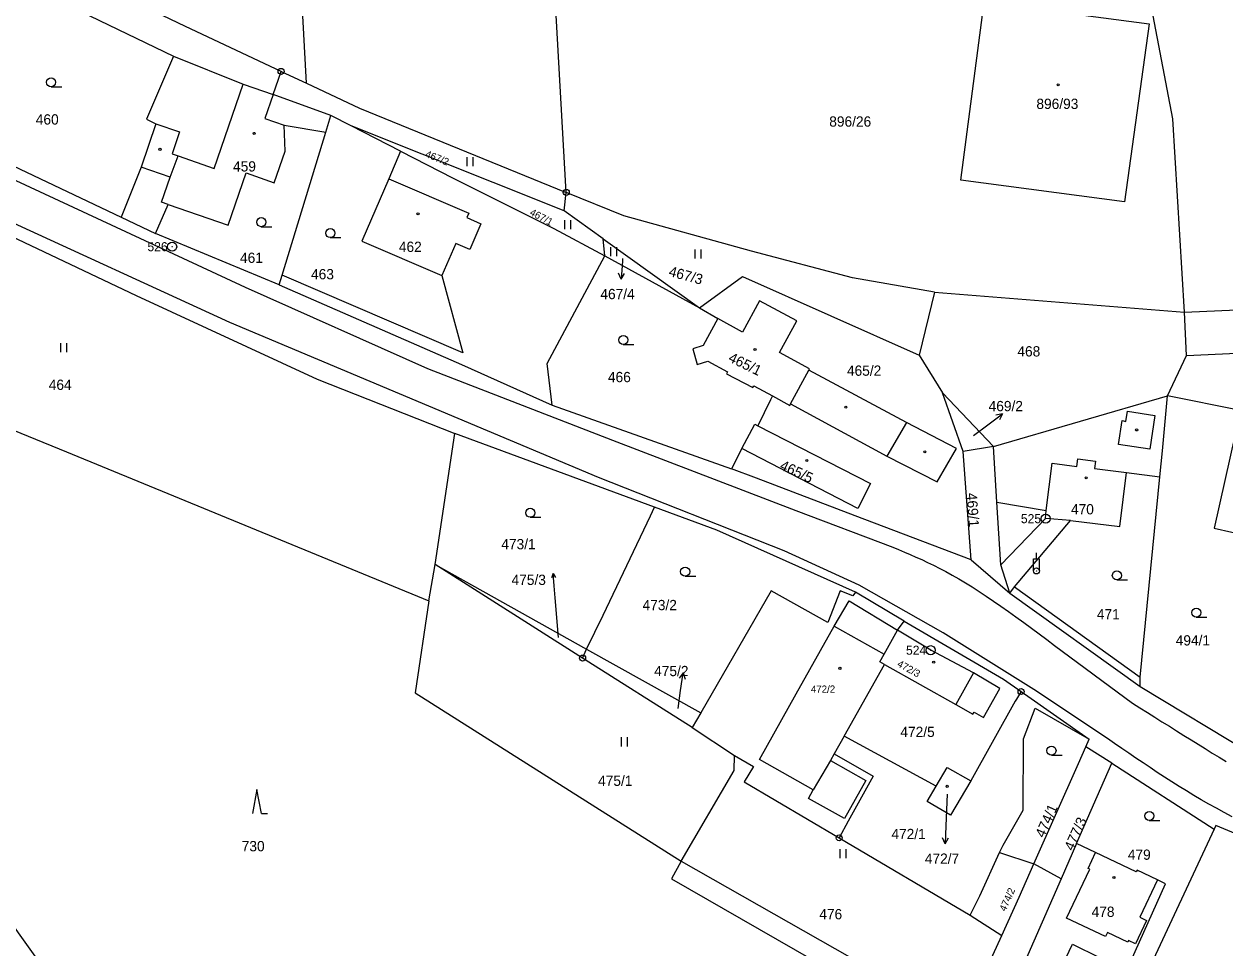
# Model space of a CAD drawing. Extents: x -504988 to -494607, y -1123820 to -1114018.
# Drawn here: x -500090 to -499891, y -1121300.2 to -1121147.2 of the extents above; entities that cross this region are included whole.
import ezdxf

# ---------------------------------------------------------------- set-up
doc = ezdxf.new("R2010")
doc.units = 0
for name, color, linetype in [('Hranice parcel', 7, 'Continuous'), ('Parcelní čísla', 7, 'Continuous'), ('Pop  PČ popisy', 7, 'Continuous'), ('Poz předměty', 7, 'Continuous'), ('Vnitřní kresba', 7, 'Continuous'), ('Značky bodu BP', 7, 'Continuous'), ('Značky budov', 7, 'Continuous'), ('Značky kultur', 7, 'Continuous')]:
    doc.layers.add(name, color=color, linetype=linetype)

msp = doc.modelspace()

# ---------------------------------------------------------------- linework, layer by layer
at = {"layer": 'Hranice parcel'}
for p, q in [((-500043.2, -1121156.99), (-500049.77, -1121041.7)), ((-500000.16, -1121175.06), (-500003.86, -1121109.89)), ((-500048.74, -1121158.82), (-500047.43, -1121155.01)), ((-500047.43, -1121155.01), (-500043.2, -1121156.99)), ((-500039.16, -1121162.33), (-500048.74, -1121158.82)), ((-500039.99, -1121165.06), (-500039.16, -1121162.33)), ((-500035.83, -1121164.04), (-500039.16, -1121162.33)), ((-500047.26, -1121188.77), (-500039.99, -1121165.06)), ((-500027.62, -1121168.24), (-500035.83, -1121164.04)), ((-500000.51, -1121178.14), (-500035.83, -1121164.04)), ((-500000.51, -1121178.14), (-500000.16, -1121175.06)), ((-500073.93, -1121179.19), (-500068.24, -1121181.86)), ((-499994.05, -1121182.76), (-500000.51, -1121178.14)), ((-500047.74, -1121190.35), (-500068.24, -1121181.86)), ((-499993.75, -1121185.57), (-499994.05, -1121182.76)), ((-499994.05, -1121182.76), (-499978.06, -1121194.18)), ((-499993.75, -1121185.57), (-499978.06, -1121194.18)), ((-500047.74, -1121190.35), (-500047.26, -1121188.77)), ((-499939.15, -1121191.59), (-499941.67, -1121202.01)), ((-499939.15, -1121191.59), (-499897.69, -1121194.93)), ((-499978.06, -1121194.18), (-499975.03, -1121195.97)), ((-499897.69, -1121194.93), (-499877.46, -1121194.02)), ((-499897.37, -1121202.07), (-499897.69, -1121194.93)), ((-499941.67, -1121202.01), (-499937.82, -1121208.25)), ((-499900.51, -1121208.79), (-499897.37, -1121202.07)), ((-499937.82, -1121208.25), (-499929.35, -1121217.17)), ((-499934.37, -1121217.96), (-499937.82, -1121208.25)), ((-499929.35, -1121217.17), (-499900.51, -1121208.79)), ((-499888.4, -1121211.17), (-499900.51, -1121208.79)), ((-500002.5, -1121210.32), (-499972.8, -1121220.83)), ((-500021.92, -1121236.71), (-500018.61, -1121215)), ((-499985.54, -1121227.21), (-500018.61, -1121215)), ((-499929.35, -1121217.17), (-499934.37, -1121217.96)), ((-499971.06, -1121217.5), (-499972.8, -1121220.83)), ((-499933.04, -1121235.92), (-499934.37, -1121217.96)), ((-500022.96, -1121242.74), (-500021.92, -1121236.71)), ((-500021.92, -1121236.71), (-499996.79, -1121250.75)), ((-499997.46, -1121252.21), (-500021.92, -1121236.71)), ((-499933.04, -1121235.92), (-499926.66, -1121241.48)), ((-499944.15, -1121246.08), (-499952.24, -1121241.3)), ((-499926.66, -1121241.48), (-499905.06, -1121256.94)), ((-499945.26, -1121247.58), (-499944.15, -1121246.08)), ((-499997.46, -1121252.21), (-499996.79, -1121250.75)), ((-499996.79, -1121250.75), (-499977.89, -1121261.29)), ((-499979.29, -1121263.72), (-499997.46, -1121252.21)), ((-499954.09, -1121265.13), (-499947.42, -1121253.25)), ((-499905.06, -1121256.94), (-499876.59, -1121274.1)), ((-499924.79, -1121257.75), (-499925.57, -1121259.01)), ((-499924.79, -1121257.75), (-499913.48, -1121265.62)), ((-499977.89, -1121261.29), (-499979.29, -1121263.72)), ((-499979.29, -1121263.72), (-499972.29, -1121268.35)), ((-499954.09, -1121265.13), (-499955.75, -1121268.08)), ((-499938.84, -1121273.43), (-499954.09, -1121265.13)), ((-499914.05, -1121266.92), (-499913.48, -1121265.62)), ((-499909.73, -1121269.63), (-499914.05, -1121266.92)), ((-499915.59, -1121282.94), (-499909.73, -1121269.63)), ((-499909.73, -1121269.63), (-499892.81, -1121280.54)), ((-499892.81, -1121280.54), (-499908.48, -1121314.08)), ((-499954.94, -1121281.99), (-499933.21, -1121294.78)), ((-499915.59, -1121282.94), (-499918.15, -1121288.76)), ((-499928.34, -1121284.42), (-499922.67, -1121286.31)), ((-499981.13, -1121285.84), (-499934.48, -1121312.29)), ((-499918.15, -1121288.76), (-499922.67, -1121286.31)), ((-499933.21, -1121294.78), (-499927.97, -1121298.18)), ((-499934.48, -1121312.29), (-499927.97, -1121298.18))]:
    msp.add_line(p, q, dxfattribs=at)
for points in [[(-499897.69, -1121194.93), (-499899.63, -1121162.9), (-499907.08, -1121123.78), (-499909.99, -1121114.32)], [(-500047.43, -1121155.01), (-500063.25, -1121147.6), (-500091.2, -1121134.17), (-500119.71, -1121120.47)], [(-500100.44, -1121135.48), (-500096.12, -1121137.57), (-500065.25, -1121152.48)], [(-499934.75, -1121173.01), (-499930.9, -1121143.57), (-499903.59, -1121147.12), (-499907.66, -1121176.61), (-499934.75, -1121173.01)], [(-500065.25, -1121152.48), (-500069.75, -1121162.94), (-500068.17, -1121163.69), (-500070.64, -1121170.87), (-500073.93, -1121179.19)], [(-500065.25, -1121152.48), (-500053.7, -1121157.11), (-500048.74, -1121158.82)], [(-500043.2, -1121156.99), (-500034.43, -1121161.09), (-500000.16, -1121175.06)], [(-500131.54, -1121163.63), (-500071.42, -1121192.12), (-500041.43, -1121205.99), (-500018.61, -1121215)], [(-500105.2, -1121163.81), (-500105.36, -1121164.28), (-500073.93, -1121179.19)], [(-500068.24, -1121181.86), (-500066.12, -1121177.06), (-500056.2, -1121180.48), (-500053.23, -1121171.84), (-500048.55, -1121173.45), (-500046.76, -1121168.25), (-500046.9, -1121163.94), (-500039.99, -1121165.06)], [(-500027.62, -1121168.24), (-500029.58, -1121172.81), (-500034.03, -1121183.15), (-500020.77, -1121188.84), (-500017.28, -1121201.66), (-500047.26, -1121188.77)], [(-500027.62, -1121168.24), (-500018.89, -1121172.71), (-500002.21, -1121181.05), (-499993.75, -1121185.57)], [(-499939.15, -1121191.59), (-499952.73, -1121189.21), (-499969.46, -1121184.79), (-499990.63, -1121178.95), (-500000.16, -1121175.06)], [(-500002.5, -1121210.32), (-500003.33, -1121203.43), (-499993.75, -1121185.57)], [(-499978.06, -1121194.18), (-499970.97, -1121189), (-499941.67, -1121202.01)], [(-500047.74, -1121190.35), (-500017.55, -1121203.56), (-500002.5, -1121210.32)], [(-500144.15, -1121193.06), (-500082.97, -1121218.02), (-500022.96, -1121242.74)], [(-499965.99, -1121208.79), (-499963.12, -1121210.36), (-499963, -1121210.11), (-499947.02, -1121218.75), (-499938.69, -1121223.02), (-499935.51, -1121217.47), (-499943.8, -1121213.18), (-499959.98, -1121204.53), (-499959.85, -1121204.29), (-499964.8, -1121201.58), (-499961.94, -1121196.35), (-499968.14, -1121193), (-499970.98, -1121198.19), (-499975.03, -1121195.97)], [(-499975.03, -1121195.97), (-499977.5, -1121200.43), (-499979.2, -1121200.96), (-499978.45, -1121203.57), (-499976.72, -1121203.04), (-499973.47, -1121204.81), (-499973.61, -1121205.11), (-499969.25, -1121207.38), (-499969.1, -1121207.09), (-499965.99, -1121208.79)], [(-499897.37, -1121202.07), (-499877.14, -1121201.15), (-499879.56, -1121212.9)], [(-500074.14, -1121320.39), (-500082.16, -1121310.01), (-500092.71, -1121295.25), (-500121.86, -1121247.48), (-500139.08, -1121217.71), (-500151.3, -1121203.4), (-500150.54, -1121201.64)], [(-499965.99, -1121208.79), (-499966.3, -1121209.42), (-499968.44, -1121213.72)], [(-499901.78, -1121222.17), (-499901.36, -1121217.88), (-499900.51, -1121208.79)], [(-499888.4, -1121211.17), (-499892.8, -1121230.67), (-499884.02, -1121232.66), (-499888.25, -1121251.39), (-499872.3, -1121255.02), (-499876.59, -1121274.1)], [(-499971.06, -1121217.5), (-499968.93, -1121213.47), (-499968.44, -1121213.72)], [(-499968.44, -1121213.72), (-499949.73, -1121223.26), (-499951.85, -1121227.42), (-499971.06, -1121217.5)], [(-499926.66, -1121241.48), (-499928.17, -1121236.76), (-499928.8, -1121226.37), (-499929.35, -1121217.17)], [(-499933.04, -1121235.92), (-499952.28, -1121228.65), (-499968.64, -1121222.41), (-499972.8, -1121220.83)], [(-499926.66, -1121241.48), (-499925.88, -1121240.43), (-499916.59, -1121229.4), (-499908.43, -1121230.42), (-499907.32, -1121221.48), (-499901.78, -1121222.17)], [(-499905.06, -1121256.94), (-499905.05, -1121255.35), (-499901.78, -1121222.17)], [(-499996.79, -1121250.75), (-499994.06, -1121245.1), (-499986.22, -1121228.65), (-499985.54, -1121227.21)], [(-499952.24, -1121241.3), (-499975.24, -1121231.02), (-499985.54, -1121227.21)], [(-499952.24, -1121241.3), (-499952.68, -1121241.92), (-499954.77, -1121241.05), (-499956.79, -1121246.33), (-499966.21, -1121241.05), (-499977.89, -1121261.29)], [(-500022.96, -1121242.74), (-500025.22, -1121257.95), (-499981.13, -1121285.84)], [(-499944.15, -1121246.08), (-499927.72, -1121255.71), (-499924.79, -1121257.75)], [(-499947.42, -1121253.25), (-499948.2, -1121252.83), (-499947.5, -1121251.56), (-499945.26, -1121247.58)], [(-499947.42, -1121253.25), (-499935.61, -1121259.89), (-499932.77, -1121261.48), (-499932.59, -1121261.15), (-499931.02, -1121262.04), (-499928.33, -1121257.24), (-499932.67, -1121254.66), (-499939.76, -1121250.9), (-499945.26, -1121247.58)], [(-499925.57, -1121259.01), (-499925.79, -1121259.36), (-499933.09, -1121272.53)], [(-499928.34, -1121284.42), (-499927.78, -1121283.19), (-499924.47, -1121277.39), (-499924.4, -1121265.59), (-499922.44, -1121260.53), (-499913.48, -1121265.62)], [(-499922.67, -1121286.31), (-499915.26, -1121269.66), (-499914.05, -1121266.92)], [(-499981.13, -1121285.84), (-499972.34, -1121270.81), (-499972.29, -1121268.35)], [(-499972.29, -1121268.35), (-499969.15, -1121270.14), (-499970.67, -1121272.73), (-499954.94, -1121281.99)], [(-499955.75, -1121268.08), (-499949.29, -1121271.75), (-499953.42, -1121279.22), (-499954.94, -1121281.99)], [(-499938.84, -1121273.43), (-499937.04, -1121270.36), (-499933.09, -1121272.53)], [(-499933.09, -1121272.53), (-499936.48, -1121278.21), (-499940.34, -1121275.99), (-499938.84, -1121273.43)], [(-499867.88, -1121290.22), (-499892.53, -1121279.95), (-499892.81, -1121280.54)], [(-499920.56, -1121308.65), (-499916.26, -1121299.61), (-499907.31, -1121303.99), (-499900.84, -1121289.59), (-499902.2, -1121288.95), (-499905.57, -1121287.35), (-499905.7, -1121287.62), (-499912.44, -1121284.43), (-499915.59, -1121282.94)], [(-499933.21, -1121294.78), (-499931.6, -1121291.6), (-499928.34, -1121284.42)], [(-499981.13, -1121285.84), (-499982.72, -1121288.8), (-499936.13, -1121315.5), (-499937.43, -1121351.46), (-499939.91, -1121358.34)], [(-499927.97, -1121298.18), (-499925.11, -1121291.8), (-499922.67, -1121286.31)], [(-499918.15, -1121288.76), (-499925.85, -1121306.27), (-499923.48, -1121307.34)]]:
    msp.add_lwpolyline(points, dxfattribs=at)
at = {"layer": 'Pop  PČ popisy'}
for p, q in [((-499990.85, -1121186.46), (-499991.06, -1121189.45)), ((-499990.82, -1121186.02), (-499990.85, -1121186.46)), ((-499991.06, -1121189.45), (-499991.49, -1121188.42)), ((-499991.06, -1121189.45), (-499990.49, -1121188.49)), ((-499930.28, -1121213.55), (-499927.88, -1121211.74)), ((-499927.88, -1121211.74), (-499928.98, -1121211.95)), ((-499927.88, -1121211.74), (-499928.38, -1121212.75)), ((-499932.7, -1121215.34), (-499930.28, -1121213.55)), ((-500002.33, -1121238.22), (-500002.6, -1121238.92)), ((-500002.15, -1121240.22), (-500002.33, -1121238.22)), ((-500002.33, -1121238.22), (-500001.93, -1121238.86)), ((-499980.8, -1121254.63), (-499981.44, -1121255.55)), ((-499981.22, -1121257.6), (-499980.8, -1121254.63)), ((-499980.8, -1121254.63), (-499980.45, -1121255.69)), ((-499981.63, -1121260.58), (-499981.22, -1121257.6)), ((-499937.02, -1121274.77), (-499937.24, -1121279.98)), ((-499937.24, -1121279.98), (-499937.35, -1121282.98)), ((-499937.35, -1121282.98), (-499937.81, -1121281.96)), ((-499937.35, -1121282.98), (-499936.81, -1121282))]:
    msp.add_line(p, q, dxfattribs=at)
msp.add_lwpolyline([(-500001.45, -1121248.82), (-500001.99, -1121242.23), (-500002.15, -1121240.22)], dxfattribs=at)
at = {"layer": 'Poz předměty'}
for p, q in [((-499922.24, -1121235.77), (-499922.24, -1121234.77)), ((-499922.74, -1121235.77), (-499921.74, -1121235.77)), ((-499922.74, -1121237.77), (-499922.74, -1121235.77)), ((-499921.74, -1121237.77), (-499921.74, -1121235.77))]:
    msp.add_line(p, q, dxfattribs=at)
for radius in [0.5, 0.0303]:
    msp.add_circle((-499922.24, -1121237.77), radius, dxfattribs=at)
at = {"layer": 'Vnitřní kresba'}
for p, q in [((-500058.51, -1121171.1), (-500053.7, -1121157.11)), ((-500048.74, -1121158.82), (-500050.12, -1121162.83)), ((-500050.12, -1121162.83), (-500046.9, -1121163.94)), ((-500068.17, -1121163.69), (-500064.25, -1121165.04)), ((-500064.25, -1121165.04), (-500065.5, -1121168.68)), ((-500065.83, -1121172.52), (-500064.5, -1121169.02)), ((-500065.5, -1121168.68), (-500064.5, -1121169.02)), ((-500064.5, -1121169.02), (-500058.51, -1121171.1)), ((-500065.83, -1121172.52), (-500070.64, -1121170.87)), ((-500092.19, -1121172.69), (-500053.36, -1121190.75)), ((-500067.26, -1121176.67), (-500065.83, -1121172.52)), ((-500029.58, -1121172.81), (-500016.33, -1121178.5)), ((-500066.12, -1121177.06), (-500067.26, -1121176.67)), ((-500055.9, -1121196.62), (-500094.76, -1121178.83)), ((-500016.33, -1121178.5), (-500016.65, -1121179.24)), ((-500016.65, -1121179.24), (-500014.31, -1121180.25)), ((-500014.31, -1121180.25), (-500016.13, -1121184.5)), ((-500018.48, -1121183.5), (-500020.77, -1121188.84)), ((-500016.13, -1121184.5), (-500018.48, -1121183.5)), ((-500053.36, -1121190.75), (-500023.19, -1121204.25)), ((-499994.82, -1121222.28), (-500055.9, -1121196.62)), ((-500023.19, -1121204.25), (-499992.49, -1121216.11)), ((-499963, -1121210.11), (-499959.98, -1121204.53)), ((-499907.41, -1121213), (-499907.16, -1121211.32)), ((-499907.16, -1121211.32), (-499902.63, -1121212)), ((-499943.8, -1121213.18), (-499947.02, -1121218.75)), ((-499908.64, -1121216.84), (-499908.04, -1121212.86)), ((-499908.04, -1121212.86), (-499907.41, -1121213)), ((-499902.63, -1121212), (-499903.46, -1121217.61)), ((-499992.49, -1121216.11), (-499962.13, -1121227.78)), ((-499903.46, -1121217.61), (-499908.64, -1121216.84)), ((-499915.56, -1121220.45), (-499915.4, -1121219.2)), ((-499915.4, -1121219.2), (-499912.47, -1121219.57)), ((-499920.63, -1121227.77), (-499919.65, -1121219.94)), ((-499919.65, -1121219.94), (-499915.56, -1121220.45)), ((-499912.47, -1121219.57), (-499912.62, -1121220.82)), ((-499912.62, -1121220.82), (-499907.32, -1121221.48)), ((-499964.07, -1121234.45), (-499994.82, -1121222.28)), ((-499928.8, -1121226.37), (-499920.63, -1121227.77)), ((-499962.13, -1121227.78), (-499946.02, -1121233.84)), ((-499928.17, -1121236.76), (-499920.72, -1121229.11)), ((-499920.72, -1121229.11), (-499920.63, -1121227.77)), ((-499916.59, -1121229.4), (-499920.72, -1121229.11)), ((-499951.63, -1121240.14), (-499964.07, -1121234.45)), ((-499937.72, -1121248.03), (-499951.63, -1121240.14)), ((-499925.88, -1121240.43), (-499905.05, -1121255.35)), ((-499955.75, -1121246.92), (-499953.27, -1121242.72)), ((-499953.27, -1121242.72), (-499945.26, -1121247.58)), ((-499962.05, -1121258.14), (-499955.75, -1121246.92)), ((-499955.75, -1121246.92), (-499947.5, -1121251.56)), ((-499922.66, -1121257.43), (-499937.72, -1121248.03)), ((-499919.23, -1121250.1), (-499906.31, -1121259.69)), ((-499932.67, -1121254.66), (-499935.61, -1121259.89)), ((-499968.15, -1121269), (-499962.05, -1121258.14)), ((-499910.45, -1121265.53), (-499922.66, -1121257.43)), ((-499959.22, -1121274.02), (-499968.15, -1121269)), ((-499955.75, -1121268.08), (-499956.38, -1121269.2)), ((-499956.38, -1121269.2), (-499959.22, -1121274.02)), ((-499956.38, -1121269.2), (-499950.53, -1121272.48)), ((-499950.53, -1121272.48), (-499954.08, -1121278.79)), ((-499960.02, -1121275.45), (-499959.22, -1121274.02)), ((-499954.08, -1121278.79), (-499960.02, -1121275.45)), ((-499913.69, -1121287.05), (-499912.44, -1121284.43)), ((-499913.41, -1121287.18), (-499913.69, -1121287.05)), ((-499917.25, -1121295.27), (-499913.41, -1121287.18)), ((-499902.2, -1121288.95), (-499905.13, -1121295.15)), ((-499910.78, -1121298.33), (-499917.25, -1121295.27)), ((-499903.99, -1121295.68), (-499905.83, -1121299.55)), ((-499905.13, -1121295.15), (-499903.99, -1121295.68)), ((-499910.46, -1121297.66), (-499910.78, -1121298.33)), ((-499907.08, -1121299.26), (-499910.46, -1121297.66)), ((-499906.96, -1121299.01), (-499907.08, -1121299.26)), ((-499905.83, -1121299.55), (-499906.96, -1121299.01))]:
    msp.add_line(p, q, dxfattribs=at)
for points in [[(-499946.02, -1121233.84), (-499945.08, -1121234.24), (-499944.13, -1121234.64), (-499943.18, -1121235.05), (-499942.23, -1121235.47), (-499941.26, -1121235.9), (-499940.28, -1121236.36), (-499939.29, -1121236.83), (-499938.27, -1121237.34), (-499937.25, -1121237.88), (-499936.2, -1121238.45), (-499935.12, -1121239.07), (-499934.02, -1121239.72), (-499932.89, -1121240.42), (-499931.73, -1121241.17), (-499930.55, -1121241.95), (-499929.35, -1121242.76), (-499928.12, -1121243.62), (-499926.89, -1121244.49), (-499925.64, -1121245.38), (-499924.36, -1121246.31), (-499923.09, -1121247.24), (-499921.81, -1121248.18), (-499920.52, -1121249.15), (-499919.23, -1121250.1)], [(-499906.31, -1121259.69), (-499905.09, -1121260.46), (-499903.86, -1121261.23), (-499902.65, -1121261.99), (-499901.44, -1121262.75), (-499900.22, -1121263.51), (-499899.02, -1121264.27), (-499897.83, -1121265.01), (-499896.62, -1121265.76), (-499895.45, -1121266.49), (-499894.28, -1121267.21), (-499893.1, -1121267.94), (-499891.95, -1121268.64), (-499890.81, -1121269.33)], [(-499889.81, -1121278.48), (-499891.12, -1121277.78), (-499892.4, -1121277.09), (-499893.66, -1121276.39), (-499894.93, -1121275.67), (-499896.16, -1121274.95), (-499897.38, -1121274.22), (-499898.61, -1121273.46), (-499899.82, -1121272.7), (-499901.01, -1121271.93), (-499902.22, -1121271.15), (-499903.4, -1121270.36), (-499904.58, -1121269.57), (-499905.77, -1121268.76), (-499906.94, -1121267.96), (-499908.1, -1121267.16), (-499909.29, -1121266.34), (-499910.45, -1121265.53)]]:
    msp.add_lwpolyline(points, dxfattribs=at)
at = {"layer": 'Značky bodu BP'}
for centre, radius in [((-500047.43, -1121155.01), 0.5), ((-500047.43, -1121155.01), 0.0303), ((-500000.16, -1121175.06), 0.5), ((-500000.16, -1121175.06), 0.0303), ((-500065.48, -1121184.06), 0.75), ((-500065.48, -1121184.06), 0.03), ((-499920.72, -1121229.11), 0.75), ((-499920.72, -1121229.11), 0.03), ((-499939.76, -1121250.9), 0.75), ((-499939.76, -1121250.9), 0.03), ((-499997.46, -1121252.21), 0.5), ((-499997.46, -1121252.21), 0.0303), ((-499924.79, -1121257.75), 0.5), ((-499924.79, -1121257.75), 0.0303), ((-499954.94, -1121281.99), 0.5), ((-499954.94, -1121281.99), 0.0303)]:
    msp.add_circle(centre, radius, dxfattribs=at)
at = {"layer": 'Značky budov'}
for centre in [(-499918.63, -1121157.23), (-500051.88, -1121165.29), (-500067.5, -1121167.93), (-500024.73, -1121178.62), (-499968.88, -1121201.08), (-499953.82, -1121210.65), (-499905.64, -1121214.41), (-499960.3, -1121219.47), (-499940.75, -1121218.03), (-499914, -1121222.35), (-499939.27, -1121252.87), (-499954.81, -1121253.91), (-499937.03, -1121273.46), (-499909.4, -1121288.56)]:
    msp.add_circle(centre, 0.175, dxfattribs=at)
at = {"layer": 'Značky kultur'}
for p, q in [((-500085.54, -1121157.57), (-500083.79, -1121157.57)), ((-500016.61, -1121170.73), (-500016.61, -1121169.23)), ((-500015.61, -1121170.73), (-500015.61, -1121169.23)), ((-500050.72, -1121180.74), (-500048.97, -1121180.74)), ((-500000.42, -1121181.14), (-500000.42, -1121179.64)), ((-499999.42, -1121181.14), (-499999.42, -1121179.64)), ((-500039.27, -1121182.56), (-500037.52, -1121182.56)), ((-499992.78, -1121185.63), (-499992.78, -1121184.13)), ((-499991.78, -1121185.63), (-499991.78, -1121184.13)), ((-499978.82, -1121186.02), (-499978.82, -1121184.52)), ((-499977.82, -1121186.02), (-499977.82, -1121184.52)), ((-500083.92, -1121201.53), (-500083.92, -1121200.03)), ((-500082.92, -1121201.53), (-500082.92, -1121200.03)), ((-499990.72, -1121200.25), (-499988.97, -1121200.25)), ((-500006.14, -1121228.89), (-500004.39, -1121228.89)), ((-499980.46, -1121238.64), (-499978.71, -1121238.64)), ((-499908.92, -1121239.27), (-499907.17, -1121239.27)), ((-499895.76, -1121245.43), (-499894.01, -1121245.43)), ((-499991.02, -1121266.83), (-499991.02, -1121265.33)), ((-499990.02, -1121266.83), (-499990.02, -1121265.33)), ((-499919.75, -1121268.29), (-499918, -1121268.29)), ((-500051.42, -1121273.96), (-500052.17, -1121277.96)), ((-500050.67, -1121277.96), (-500051.42, -1121273.96)), ((-500050.67, -1121277.96), (-500049.67, -1121277.96)), ((-499903.55, -1121279.1), (-499901.8, -1121279.1)), ((-499954.78, -1121285.35), (-499954.78, -1121283.85)), ((-499953.78, -1121285.35), (-499953.78, -1121283.85))]:
    msp.add_line(p, q, dxfattribs=at)
for centre in [(-500085.54, -1121156.82), (-500050.72, -1121179.99), (-500039.27, -1121181.81), (-499990.72, -1121199.5), (-500006.14, -1121228.14), (-499980.46, -1121237.89), (-499908.92, -1121238.52), (-499895.76, -1121244.68), (-499919.75, -1121267.54), (-499903.55, -1121278.35)]:
    msp.add_circle(centre, 0.75, dxfattribs=at)

# ---------------------------------------------------------------- texts
at = {"layer": 'Parcelní čísla'}
for s, height, p in [('896/93', 1.7, (-499922.25, -1121161.24)), ('460', 1.7, (-500088.08, -1121163.82)), ('896/26', 1.7, (-499956.58, -1121164.17)), ('459', 1.7, (-500055.39, -1121171.6)), ('462', 1.7, (-500027.91, -1121184.92)), ('461', 1.7, (-500054.23, -1121186.74)), ('463', 1.7, (-500042.46, -1121189.46)), ('467/4', 1.7, (-499994.51, -1121192.75)), ('468', 1.7, (-499925.4, -1121202.24)), ('466', 1.7, (-499993.26, -1121206.5)), ('465/2', 1.7, (-499953.65, -1121205.44)), ('464', 1.7, (-500085.93, -1121207.78)), ('469/2', 1.7, (-499930.17, -1121211.31)), ('470', 1.7, (-499916.52, -1121228.4)), ('473/1', 1.7, (-500010.93, -1121234.18)), ('475/3', 1.7, (-500009.23, -1121240.09)), ('473/2', 1.7, (-499987.52, -1121244.27)), ('471', 1.7, (-499912.23, -1121245.79)), ('494/1', 1.7, (-499899.16, -1121250.12)), ('475/2', 1.7, (-499985.6, -1121255.2)), ('472/2', 1.2, (-499959.62, -1121257.95)), ('472/5', 1.7, (-499944.79, -1121265.28)), ('475/1', 1.7, (-499994.89, -1121273.38)), ('472/1', 1.7, (-499946.28, -1121282.2)), ('730', 1.7, (-500053.95, -1121284.21)), ('472/7', 1.7, (-499940.74, -1121286.28)), ('479', 1.7, (-499907.1, -1121285.62)), ('476', 1.7, (-499958.23, -1121295.48)), ('478', 1.7, (-499913.1, -1121295.08))]:
    msp.add_text(s, height=height, dxfattribs=at).set_placement(p)
for s, height, rotation, p in [('467/2', 1.2, 338, (-500023.64, -1121169.15)), ('467/1', 1.2, 332, (-500006.33, -1121178.74)), ('467/3', 1.7, 345, (-499983.3, -1121188.89)), ('465/1', 1.7, 334, (-499973.44, -1121203)), ('465/5', 1.7, 335, (-499964.92, -1121220.87)), ('469/1', 1.7, 274, (-499933.82, -1121224.89)), ('472/3', 1.2, 331, (-499945.44, -1121253.51)), ('474/1', 1.7, 66, (-499920.98, -1121282.1)), ('477/3', 1.7, 66, (-499916.17, -1121284.26)), ('474/2', 1.2, 66, (-499927.36, -1121294.27))]:
    msp.add_text(s, height=height, rotation=rotation, dxfattribs=at).set_placement(p)
at = {"layer": 'Značky bodu BP'}
for s, p in [('526', (-500069.58, -1121184.81)), ('525', (-499924.82, -1121229.86)), ('524', (-499943.86, -1121251.65))]:
    msp.add_text(s, height=1.5, dxfattribs=at).set_placement(p)

doc.saveas('drawing.dxf')
